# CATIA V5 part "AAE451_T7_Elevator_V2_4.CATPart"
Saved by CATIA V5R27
Part number: Elevator
Bounding box of the stored display mesh (mm): x 0 to 69.698, y -12.436 to 0.05, z -114.985 to 0
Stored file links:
  W:\AAE 451\AAE451_T7_TailAssembly_V2\AAE451_T7_Elevator_V2_4.CATPart
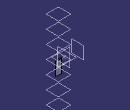
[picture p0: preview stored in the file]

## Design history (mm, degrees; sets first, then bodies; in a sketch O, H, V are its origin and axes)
Set1 "GeometryFromExcel"
  Point1: (1, 0.001, 0)
  Point2: (0.95, 0.0067, 0)
  Point3: (0.9, 0.0121, 0)
  Point4: (0.8, 0.0219, 0)
  Point5: (0.7, 0.0305, 0)
  Point6: (0.6, 0.038, 0)
  Point7: (0.5, 0.0441, 0)
  Point8: (0.4, 0.0484, 0)
  Point9: (0.3, 0.05, 0)
  Point10: (0.25, 0.0495, 0)
  Point11: (0.2, 0.0478, 0)
  Point12: (0.15, 0.0445, 0)
  Point13: (0.1, 0.039, 0)
  Point14: (0.075, 0.035, 0)
  Point15: (0.05, 0.0296, 0)
  Point16: (0.025, 0.0218, 0)
  Point17: (0.0125, 0.0158, 0)
  Point18: (0, 0, 0)
  Point19: (0.0125, -0.0158, 0)
  Point20: (0.025, -0.0218, 0)
  Point21: (0.05, -0.0296, 0)
  Point22: (0.075, -0.035, 0)
  Point23: (0.1, -0.039, 0)
  Point24: (0.15, -0.0445, 0)
  Point25: (0.2, -0.0478, 0)
  Point26: (0.25, -0.0495, 0)
  Point27: (0.3, -0.05, 0)
  Point28: (0.4, -0.0484, 0)
  Point29: (0.5, -0.0441, 0)
  Point30: (0.6, -0.038, 0)
  Point31: (0.7, -0.0305, 0)
  Point32: (0.8, -0.0219, 0)
  Point33: (0.9, -0.0121, 0)
  Point34: (0.95, -0.0067, 0)
  Point35: (1, -0.001, 0)
  Point36: (1, 0.001, 0)
  Point37: (0.95, 0.0067, 0)
  Point38: (0.9, 0.0121, 0)
  Point39: (0.8, 0.0219, 0)
  Point40: (0.7, 0.0305, 0)
  Point41: (0.6, 0.038, 0)
  Point42: (0.5, 0.0441, 0)
  Point43: (0.4, 0.0484, 0)
  Point44: (0.3, 0.05, 0)
  Point45: (0.25, 0.0495, 0)
  Point46: (0.2, 0.0478, 0)
  Point47: (0.15, 0.0445, 0)
  Point48: (0.1, 0.039, 0)
  Point49: (0.075, 0.035, 0)
  Point50: (0.05, 0.0296, 0)
  Point51: (0.025, 0.0218, 0)
  Point52: (0.0125, 0.0158, 0)
  Point53: (0, 0, 0)
  Point54: (0.0125, -0.0158, 0)
  Point55: (0.025, -0.0218, 0)
  Point56: (0.05, -0.0296, 0)
  Point57: (0.075, -0.035, 0)
  Point58: (0.1, -0.039, 0)
  Point59: (0.15, -0.0445, 0)
  Point60: (0.2, -0.0478, 0)
  Point61: (0.25, -0.0495, 0)
  Point62: (0.3, -0.05, 0)
  Point63: (0.4, -0.0484, 0)
  Point64: (0.5, -0.0441, 0)
  Point65: (0.6, -0.038, 0)
  Point66: (0.7, -0.0305, 0)
  Point67: (0.8, -0.0219, 0)
  Point68: (0.9, -0.0121, 0)
  Point69: (0.95, -0.0067, 0)
  Point70: (1, -0.001, 0)
  Curve1: Elements (Point36; Point37; Point38; Point39; Point40; Point41; Point42; Point43; Point44; Point45; Point46; Point47; Point48; Point49; Point50; Point51; Point52; Point53; Point54; Point55; Point56; Point57; Point58; Point59; Point60; Point61; Point62; Point63; Point64; Point65; Point66; Point67; Point68; Point69; Point70)
  Sketch1 on xy-plane, origin (0, 0, 0), H (1, 0, 0), V (0, 1, 0)
    projected curve E1 from edge of Curve1
    point P1 (1, 0.0011)
    line L1 (1, 0.0011) -> (1, -0.001)
    point P3 (1, 0.001)
    point P4 (1, -0.001)
    reference projected point E2 (1, 0.001) from Point1
    reference projected point E3 (1, -0.001) from Point35
    coincidence: P3 E2, P4 E3, P1 P3
Body1 (main body)
  Pad1: profile Sketch1, direction (0, 0, 1), length 1.5215, mirrored extent
  Scaling1: Reference Point40, Ratio 230, ToTransfor Pad1
  Plane1: type Offset, RefPlane yz-plane, Offset 120, reversed
  Sketch2 on xy-plane, origin (0, 0, 0), H (1, 0, 0), V (0, 1, 0)
    reference projected line E1 (69.6979, -7.2245) -> (69.698, -6.7499) from edge [face of Pad1 from Sketch1.L1 | end face of Pad1]
    line L1 (13.6994, -1.0636) -> (13.6965, -12.9194)
    projected curve E2 from edge [face of Pad1 from Sketch1.E1 | end face of Pad1]
    projected curve E3 from edge [face of Pad1 from Sketch1.E1 | end face of Pad1]
    distance E1 L1 = 56
  Pocket1: profile Sketch2, direction (0, 0, -1), through (limit type 3), opposite side through (limit type 3)
  Fillet1: radius 5, on edge [face of Pad1 from Sketch1.E1 | face of Pocket1 from Sketch2.L1]; edge [face of Pocket1 from Sketch2.L1 | face of Pad1 from Sketch1.E1]
  Sketch3 on zx-plane, origin (0, 0, 0), H (-1, 0, 0), V (0, 0, 1)
    line L1 (-135.4649, -344.945) -> (50.2623, -344.945)
    line L2 (50.2623, -344.945) -> (50.2623, -349.945)
    line L3 (50.2623, -349.945) -> (-135.4649, -349.945)
    line L4 (-135.4649, -349.945) -> (-135.4649, -344.945)
    line L5 (-146.4826, 349.945) -> (56.5582, 349.945)
    line L6 (56.5582, 349.945) -> (56.5582, 344.945)
    line L7 (56.5582, 344.945) -> (-146.4826, 344.945)
    line L8 (-146.4826, 344.945) -> (-146.4826, 349.945)
    reference projected line E1 (-69.7, 349.945) -> (160.3, 349.945) from edge [face of Pad1 from Sketch1.E1 | end face of Pad1]
    reference projected line E2 (-69.7, -349.945) -> (160.3, -349.945) from edge [start face of Pad1 | face of Pad1 from Sketch1.E1]
    distance L7 L5 = 5
    horizontal: L1 H, L3 H, L5 H, L7 H
    vertical: L2 V, L4 V, L6 V, L8 V
    coincidence: L5 E1, L3 E2
    symmetry: L7 L1 H
  Pocket2: profile Sketch3, direction (0, -1, 0), through (limit type 3)
  Sketch4 on face of Pocket1 from Sketch2.L1, origin (13.6996, -0.0033, 0), H (-0.0002, -1, 0), V (0, 0, 1)
    line L1 (6.4867, 8) -> (7.4867, 8)
    line L2 (7.4867, 8) -> (7.4867, -8)
    line L3 (7.4867, -8) -> (6.4867, -8)
    line L4 (6.4867, -8) -> (6.4867, 8)
    construction line L5 (6.9867, 7.1913) -> (6.9867, -6.7162)
    reference projected line E1 (1.5418, 344.945) -> (1.5418, -344.945) from edge [face of Pad1 from Sketch1.E1 | face of Fillet1]
    reference projected line E2 (12.4317, 344.945) -> (12.4317, -344.945) from edge [face of Fillet1 | face of Pad1 from Sketch1.E1]
    distance L4 L2 = 1
    distance L1 L3 = 16
    horizontal: L1 H, L3 H
    vertical: L2 V, L4 V
    symmetry: L3 L1 H, L4 L2 L5, E1 E2 L5
  Pocket3: profile Sketch4, direction (1, -0.0002, 0), length 13.7
  RectPattern1: of Pocket3, direction 1 instances 2, spacing 230, along zx-plane
  Mirror1: of RectPattern1, about xy-plane
  Plane2: type Offset, RefPlane face of Pocket2 from Sketch3.L7, Offset 0, reversed
  Plane3: type Offset, RefPlane face of Pocket2 from Sketch3.L1, Offset 0, reversed
  Plane4: type Offset, RefPlane Plane3, Offset 114.98
  Plane5: type Offset, RefPlane Plane4, Offset 114.98
  Plane6: type Offset, RefPlane Plane5, Offset 114.98
  Plane7: type Offset, RefPlane Plane6, Offset 114.98
  Plane8: type Offset, RefPlane Plane7, Offset 114.98
  Split1: SplitPlane Plane5
  Split2: SplitPlane Plane6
